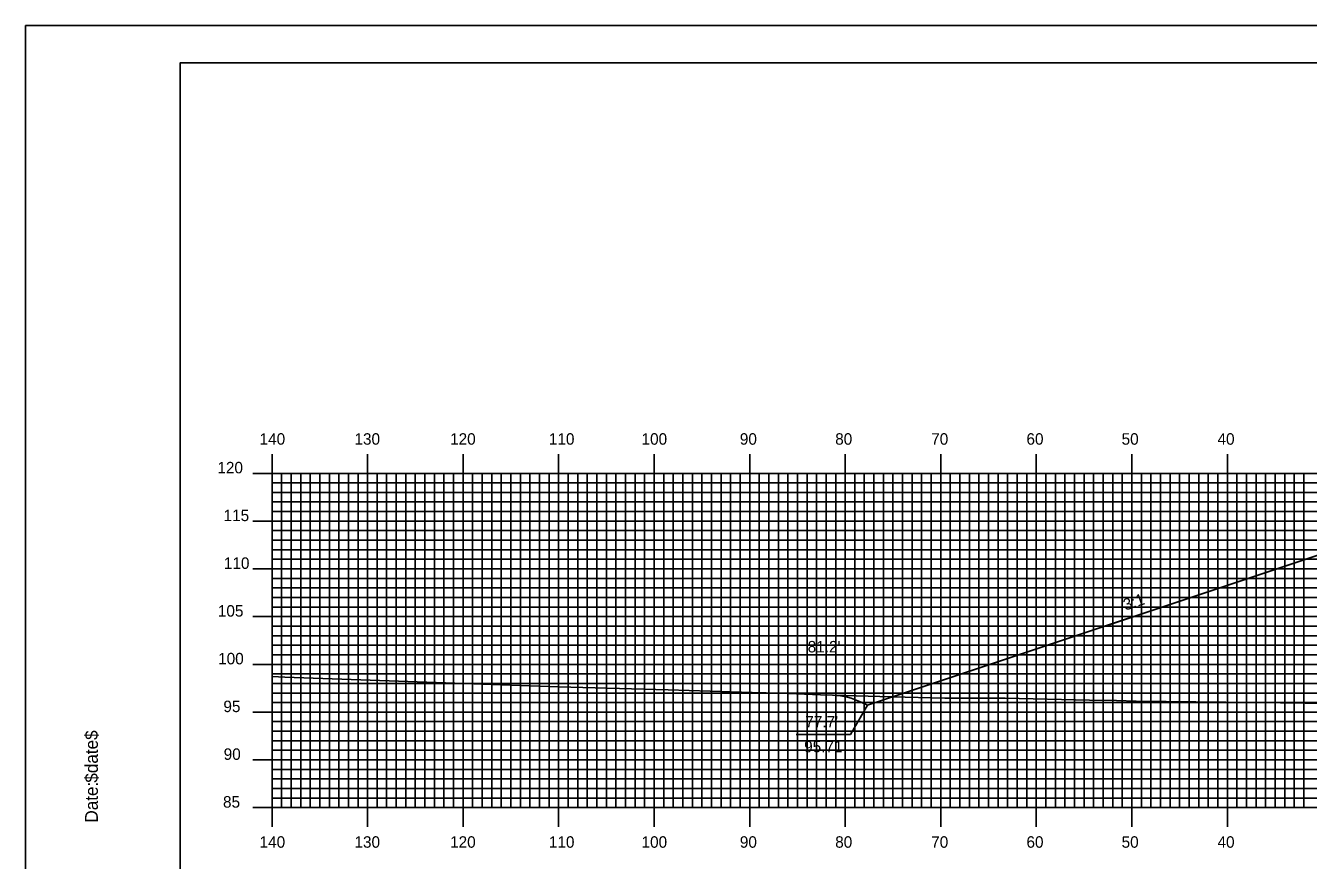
# Model space of a CAD drawing. Extents: x 1786582 to 1786926, y 442591 to 442811.
# Drawn here: x 1786582.3 to 1786716.6, y 442723.1 to 442810.5 of the extents above; entities that cross this region are included whole.
import ezdxf

# ---------------------------------------------------------------- set-up
doc = ezdxf.new("R2010")
doc.units = 0
for name, color, linetype in [('ANNOTATION', 7, 'Continuous'), ('BORDER', 7, 'Continuous'), ('D_Roadway_Centerline', 7, 'Continuous'), ('D_Roadway_FinishedGrade', 7, 'Continuous'), ('D_Roadway_SlopeLines', 7, 'Continuous'), ('D_Text_Standard', 7, 'Continuous'), ('H_V ANNOTATION', 7, 'Continuous'), ('MAJOR', 7, 'Continuous'), ('MINOR', 7, 'Continuous'), ('PLOT BOUNDARY', 7, 'Continuous'), ('S_Roadway_Centerline', 7, 'Continuous')]:
    doc.layers.add(name, color=color, linetype=linetype)

msp = doc.modelspace()

# ---------------------------------------------------------------- linework, layer by layer
at = {"layer": 'ANNOTATION'}
msp.add_lwpolyline([(1786662.93, 442736.34), (1786668.62, 442736.34), (1786670.4, 442739.38)], dxfattribs=at)
at = {"layer": 'BORDER'}
msp.add_lwpolyline([(1786598.48, 442596.67), (1786918.48, 442596.67), (1786918.48, 442806.67), (1786598.48, 442806.67)], close=True, dxfattribs=at)
at = {"layer": 'D_Roadway_Centerline'}
msp.add_lwpolyline([(1786673.07, 442740.26), (1786717.68, 442755.13), (1786725.08, 442757.6), (1786728.08, 442757.72), (1786736.08, 442758.04), (1786748.08, 442758.3), (1786760.08, 442758.57), (1786768.08, 442758.25), (1786771.08, 442758.13), (1786776.83, 442755.73), (1786816.52, 442739.19)], dxfattribs=at)
at = {"layer": 'D_Roadway_FinishedGrade'}
msp.add_line((1786670.4, 442739.38), (1786669.75, 442739.7), dxfattribs=at)
msp.add_arc((1786666.62, 442733.44), 7, 63.4349, 88.3839, dxfattribs=at)
at = {"layer": 'D_Roadway_SlopeLines'}
msp.add_lwpolyline([(1786725.08, 442757.6), (1786670.4, 442739.38)], dxfattribs=at)
at = {"layer": 'MAJOR'}
for p, q in [((1786608.08, 442765.67), (1786608.08, 442763.67)), ((1786618.08, 442765.67), (1786618.08, 442763.67)), ((1786628.08, 442765.67), (1786628.08, 442763.67)), ((1786638.08, 442765.67), (1786638.08, 442763.67)), ((1786648.08, 442765.67), (1786648.08, 442763.67)), ((1786658.08, 442765.67), (1786658.08, 442763.67)), ((1786668.08, 442765.67), (1786668.08, 442763.67)), ((1786678.08, 442765.67), (1786678.08, 442763.67)), ((1786688.08, 442765.67), (1786688.08, 442763.67)), ((1786698.08, 442765.67), (1786698.08, 442763.67)), ((1786708.08, 442765.67), (1786708.08, 442763.67)), ((1786606.07, 442763.67), (1786608.08, 442763.67)), ((1786608.08, 442763.67), (1786888.08, 442763.67)), ((1786608.08, 442728.67), (1786608.08, 442763.67)), ((1786608.08, 442728.67), (1786608.08, 442763.67)), ((1786608.08, 442763.67), (1786888.08, 442763.67)), ((1786618.08, 442728.67), (1786618.08, 442763.67)), ((1786628.08, 442728.67), (1786628.08, 442763.67)), ((1786638.08, 442728.67), (1786638.08, 442763.67)), ((1786648.08, 442728.67), (1786648.08, 442763.67)), ((1786658.08, 442728.67), (1786658.08, 442763.67)), ((1786668.08, 442728.67), (1786668.08, 442763.67)), ((1786678.08, 442728.67), (1786678.08, 442763.67)), ((1786688.08, 442728.67), (1786688.08, 442763.67)), ((1786698.08, 442728.67), (1786698.08, 442763.67)), ((1786708.08, 442728.67), (1786708.08, 442763.67)), ((1786606.07, 442758.67), (1786608.08, 442758.67)), ((1786608.08, 442758.67), (1786888.08, 442758.67)), ((1786606.07, 442753.67), (1786608.08, 442753.67)), ((1786608.08, 442753.67), (1786888.08, 442753.67)), ((1786606.07, 442748.67), (1786608.08, 442748.67)), ((1786608.08, 442748.67), (1786888.08, 442748.67)), ((1786606.07, 442743.67), (1786608.08, 442743.67)), ((1786608.08, 442743.67), (1786888.08, 442743.67)), ((1786606.07, 442738.67), (1786608.08, 442738.67)), ((1786608.08, 442738.67), (1786888.08, 442738.67)), ((1786606.07, 442733.67), (1786608.08, 442733.67)), ((1786608.08, 442733.67), (1786888.08, 442733.67)), ((1786606.07, 442728.67), (1786608.08, 442728.67)), ((1786608.08, 442728.67), (1786888.08, 442728.67)), ((1786608.08, 442728.67), (1786888.08, 442728.67)), ((1786608.08, 442726.66), (1786608.08, 442728.67)), ((1786618.08, 442726.66), (1786618.08, 442728.67)), ((1786628.08, 442726.66), (1786628.08, 442728.67)), ((1786638.08, 442726.66), (1786638.08, 442728.67)), ((1786648.08, 442726.66), (1786648.08, 442728.67)), ((1786658.08, 442726.66), (1786658.08, 442728.67)), ((1786668.08, 442726.66), (1786668.08, 442728.67)), ((1786678.08, 442726.66), (1786678.08, 442728.67)), ((1786688.08, 442726.66), (1786688.08, 442728.67)), ((1786698.08, 442726.66), (1786698.08, 442728.67)), ((1786708.08, 442726.66), (1786708.08, 442728.67))]:
    msp.add_line(p, q, dxfattribs=at)
at = {"layer": 'MINOR'}
for p, q in [((1786609.08, 442728.67), (1786609.08, 442763.67)), ((1786610.08, 442728.67), (1786610.08, 442763.67)), ((1786611.08, 442728.67), (1786611.08, 442763.67)), ((1786612.08, 442728.67), (1786612.08, 442763.67)), ((1786613.08, 442728.67), (1786613.08, 442763.67)), ((1786614.08, 442728.67), (1786614.08, 442763.67)), ((1786615.08, 442728.67), (1786615.08, 442763.67)), ((1786616.08, 442728.67), (1786616.08, 442763.67)), ((1786617.08, 442728.67), (1786617.08, 442763.67)), ((1786619.08, 442728.67), (1786619.08, 442763.67)), ((1786620.08, 442728.67), (1786620.08, 442763.67)), ((1786621.08, 442728.67), (1786621.08, 442763.67)), ((1786622.08, 442728.67), (1786622.08, 442763.67)), ((1786623.08, 442728.67), (1786623.08, 442763.67)), ((1786624.08, 442728.67), (1786624.08, 442763.67)), ((1786625.08, 442728.67), (1786625.08, 442763.67)), ((1786626.08, 442728.67), (1786626.08, 442763.67)), ((1786627.08, 442728.67), (1786627.08, 442763.67)), ((1786629.08, 442728.67), (1786629.08, 442763.67)), ((1786630.08, 442728.67), (1786630.08, 442763.67)), ((1786631.08, 442728.67), (1786631.08, 442763.67)), ((1786632.08, 442728.67), (1786632.08, 442763.67)), ((1786633.08, 442728.67), (1786633.08, 442763.67)), ((1786634.08, 442728.67), (1786634.08, 442763.67)), ((1786635.08, 442728.67), (1786635.08, 442763.67)), ((1786636.08, 442728.67), (1786636.08, 442763.67)), ((1786637.08, 442728.67), (1786637.08, 442763.67)), ((1786639.08, 442728.67), (1786639.08, 442763.67)), ((1786640.08, 442728.67), (1786640.08, 442763.67)), ((1786641.08, 442728.67), (1786641.08, 442763.67)), ((1786642.08, 442728.67), (1786642.08, 442763.67)), ((1786643.08, 442728.67), (1786643.08, 442763.67)), ((1786644.08, 442728.67), (1786644.08, 442763.67)), ((1786645.08, 442728.67), (1786645.08, 442763.67)), ((1786646.08, 442728.67), (1786646.08, 442763.67)), ((1786647.08, 442728.67), (1786647.08, 442763.67)), ((1786649.08, 442728.67), (1786649.08, 442763.67)), ((1786650.08, 442728.67), (1786650.08, 442763.67)), ((1786651.08, 442728.67), (1786651.08, 442763.67)), ((1786652.08, 442728.67), (1786652.08, 442763.67)), ((1786653.08, 442728.67), (1786653.08, 442763.67)), ((1786654.08, 442728.67), (1786654.08, 442763.67)), ((1786655.08, 442728.67), (1786655.08, 442763.67)), ((1786656.08, 442728.67), (1786656.08, 442763.67)), ((1786657.08, 442728.67), (1786657.08, 442763.67)), ((1786659.08, 442728.67), (1786659.08, 442763.67)), ((1786660.08, 442728.67), (1786660.08, 442763.67)), ((1786661.08, 442728.67), (1786661.08, 442763.67)), ((1786662.08, 442728.67), (1786662.08, 442763.67)), ((1786663.08, 442728.67), (1786663.08, 442763.67)), ((1786664.08, 442728.67), (1786664.08, 442763.67)), ((1786665.08, 442728.67), (1786665.08, 442763.67)), ((1786666.08, 442728.67), (1786666.08, 442763.67)), ((1786667.08, 442728.67), (1786667.08, 442763.67)), ((1786669.08, 442728.67), (1786669.08, 442763.67)), ((1786670.08, 442728.67), (1786670.08, 442763.67)), ((1786671.08, 442728.67), (1786671.08, 442763.67)), ((1786672.08, 442728.67), (1786672.08, 442763.67)), ((1786673.08, 442728.67), (1786673.08, 442763.67)), ((1786674.08, 442728.67), (1786674.08, 442763.67)), ((1786675.08, 442728.67), (1786675.08, 442763.67)), ((1786676.08, 442728.67), (1786676.08, 442763.67)), ((1786677.08, 442728.67), (1786677.08, 442763.67)), ((1786679.08, 442728.67), (1786679.08, 442763.67)), ((1786680.08, 442728.67), (1786680.08, 442763.67)), ((1786681.08, 442728.67), (1786681.08, 442763.67)), ((1786682.08, 442728.67), (1786682.08, 442763.67)), ((1786683.08, 442728.67), (1786683.08, 442763.67)), ((1786684.08, 442728.67), (1786684.08, 442763.67)), ((1786685.08, 442728.67), (1786685.08, 442763.67)), ((1786686.08, 442728.67), (1786686.08, 442763.67)), ((1786687.08, 442728.67), (1786687.08, 442763.67)), ((1786689.08, 442728.67), (1786689.08, 442763.67)), ((1786690.08, 442728.67), (1786690.08, 442763.67)), ((1786691.08, 442728.67), (1786691.08, 442763.67)), ((1786692.08, 442728.67), (1786692.08, 442763.67)), ((1786693.08, 442728.67), (1786693.08, 442763.67)), ((1786694.08, 442728.67), (1786694.08, 442763.67)), ((1786695.08, 442728.67), (1786695.08, 442763.67)), ((1786696.08, 442728.67), (1786696.08, 442763.67)), ((1786697.08, 442728.67), (1786697.08, 442763.67)), ((1786699.08, 442728.67), (1786699.08, 442763.67)), ((1786700.08, 442728.67), (1786700.08, 442763.67)), ((1786701.08, 442728.67), (1786701.08, 442763.67)), ((1786702.08, 442728.67), (1786702.08, 442763.67)), ((1786703.08, 442728.67), (1786703.08, 442763.67)), ((1786704.08, 442728.67), (1786704.08, 442763.67)), ((1786705.08, 442728.67), (1786705.08, 442763.67)), ((1786706.08, 442728.67), (1786706.08, 442763.67)), ((1786707.08, 442728.67), (1786707.08, 442763.67)), ((1786709.08, 442728.67), (1786709.08, 442763.67)), ((1786710.08, 442728.67), (1786710.08, 442763.67)), ((1786711.08, 442728.67), (1786711.08, 442763.67)), ((1786712.08, 442728.67), (1786712.08, 442763.67)), ((1786713.08, 442728.67), (1786713.08, 442763.67)), ((1786714.08, 442728.67), (1786714.08, 442763.67)), ((1786715.08, 442728.67), (1786715.08, 442763.67)), ((1786716.08, 442728.67), (1786716.08, 442763.67)), ((1786608.08, 442762.67), (1786888.08, 442762.67)), ((1786608.08, 442762.67), (1786610.08, 442762.67)), ((1786608.08, 442761.67), (1786888.08, 442761.67)), ((1786608.08, 442761.67), (1786610.08, 442761.67)), ((1786608.08, 442760.67), (1786888.08, 442760.67)), ((1786608.08, 442760.67), (1786610.08, 442760.67)), ((1786608.08, 442759.67), (1786888.08, 442759.67)), ((1786608.08, 442759.67), (1786610.08, 442759.67)), ((1786608.08, 442757.67), (1786888.08, 442757.67)), ((1786608.08, 442757.67), (1786610.08, 442757.67)), ((1786608.08, 442756.67), (1786888.08, 442756.67)), ((1786608.08, 442756.67), (1786610.08, 442756.67)), ((1786608.08, 442755.67), (1786888.08, 442755.67)), ((1786608.08, 442755.67), (1786610.08, 442755.67)), ((1786608.08, 442754.67), (1786888.08, 442754.67)), ((1786608.08, 442754.67), (1786610.08, 442754.67)), ((1786608.08, 442752.67), (1786888.08, 442752.67)), ((1786608.08, 442752.67), (1786610.08, 442752.67)), ((1786608.08, 442751.67), (1786888.08, 442751.67)), ((1786608.08, 442751.67), (1786610.08, 442751.67)), ((1786608.08, 442750.67), (1786888.08, 442750.67)), ((1786608.08, 442750.67), (1786610.08, 442750.67)), ((1786608.08, 442749.67), (1786888.08, 442749.67)), ((1786608.08, 442749.67), (1786610.08, 442749.67)), ((1786608.08, 442747.67), (1786888.08, 442747.67)), ((1786608.08, 442747.67), (1786610.08, 442747.67)), ((1786608.08, 442746.67), (1786888.08, 442746.67)), ((1786608.08, 442746.67), (1786610.08, 442746.67)), ((1786608.08, 442745.67), (1786888.08, 442745.67)), ((1786608.08, 442745.67), (1786610.08, 442745.67)), ((1786608.08, 442744.67), (1786888.08, 442744.67)), ((1786608.08, 442744.67), (1786610.08, 442744.67)), ((1786608.08, 442742.67), (1786888.08, 442742.67)), ((1786608.08, 442742.67), (1786610.08, 442742.67)), ((1786608.08, 442741.67), (1786888.08, 442741.67)), ((1786608.08, 442741.67), (1786610.08, 442741.67)), ((1786608.08, 442740.67), (1786888.08, 442740.67)), ((1786608.08, 442740.67), (1786610.08, 442740.67)), ((1786608.08, 442739.67), (1786888.08, 442739.67)), ((1786608.08, 442739.67), (1786610.08, 442739.67)), ((1786608.08, 442737.67), (1786888.08, 442737.67)), ((1786608.08, 442737.67), (1786610.08, 442737.67)), ((1786608.08, 442736.67), (1786888.08, 442736.67)), ((1786608.08, 442736.67), (1786610.08, 442736.67)), ((1786608.08, 442735.67), (1786888.08, 442735.67)), ((1786608.08, 442735.67), (1786610.08, 442735.67)), ((1786608.08, 442734.67), (1786888.08, 442734.67)), ((1786608.08, 442734.67), (1786610.08, 442734.67)), ((1786608.08, 442732.67), (1786888.08, 442732.67)), ((1786608.08, 442732.67), (1786610.08, 442732.67)), ((1786608.08, 442731.67), (1786888.08, 442731.67)), ((1786608.08, 442731.67), (1786610.08, 442731.67)), ((1786608.08, 442730.67), (1786888.08, 442730.67)), ((1786608.08, 442730.67), (1786610.08, 442730.67)), ((1786608.08, 442729.67), (1786888.08, 442729.67)), ((1786608.08, 442729.67), (1786610.08, 442729.67))]:
    msp.add_line(p, q, dxfattribs=at)
at = {"layer": 'PLOT BOUNDARY'}
msp.add_lwpolyline([(1786582.29, 442590.55), (1786922.29, 442590.55), (1786922.29, 442810.55), (1786582.29, 442810.55)], close=True, dxfattribs=at)
at = {"layer": 'S_Roadway_Centerline'}
msp.add_lwpolyline([(1786608.08, 442742.39), (1786609.43, 442742.32), (1786618.36, 442742.01), (1786637.09, 442741.35), (1786638.06, 442741.31), (1786649.55, 442740.99), (1786658.34, 442740.71), (1786661.31, 442740.64), (1786665.49, 442740.48), (1786672.97, 442740.27), (1786678.49, 442740.14), (1786684.81, 442740.12), (1786693.65, 442739.92), (1786696.47, 442739.88), (1786698.54, 442739.83), (1786711.06, 442739.68), (1786718.81, 442739.58)], dxfattribs=at)

# ---------------------------------------------------------------- texts
at = {"layer": 'ANNOTATION'}
msp.add_text('3:1', height=1.2, rotation=18.4349, dxfattribs=at).set_placement((1786697.41, 442749.29))
for s, p in [("77.7' ", (1786663.9, 442737.06)), ('95.71', (1786663.78, 442734.46))]:
    msp.add_text(s, height=1.2, dxfattribs=at).set_placement(p)
at = {"layer": 'BORDER'}
for s, p in [('$date$', (1786589.85, 442731.28)), ('Date:', (1786589.85, 442727.1))]:
    msp.add_text(s, height=1.339, rotation=90, dxfattribs=at).set_placement(p)
at = {"layer": 'D_Text_Standard'}
msp.add_text("81.2'", height=1.2, dxfattribs=at).set_placement((1786664.15, 442744.92))
at = {"layer": 'H_V ANNOTATION'}
for s, p in [('140', (1786606.78, 442766.67)), ('130', (1786616.71, 442766.67)), ('120', (1786626.72, 442766.67)), ('110', (1786637.06, 442766.67)), ('100', (1786646.76, 442766.67)), ('90', (1786657.05, 442766.67)), ('80', (1786667.03, 442766.67)), ('70', (1786677.08, 442766.67)), ('60', (1786687.05, 442766.67)), ('50', (1786697.01, 442766.67)), ('40', (1786707.05, 442766.67)), ('120', (1786602.36, 442763.67)), ('115', (1786603.01, 442758.67)), ('110', (1786603.04, 442753.67)), ('105', (1786602.41, 442748.67)), ('100', (1786602.44, 442743.67)), ('95', (1786602.99, 442738.67)), ('90', (1786603.02, 442733.67)), ('85', (1786602.95, 442728.67)), ('140', (1786606.78, 442724.47)), ('130', (1786616.71, 442724.47)), ('120', (1786626.72, 442724.47)), ('110', (1786637.06, 442724.47)), ('100', (1786646.76, 442724.47)), ('90', (1786657.05, 442724.47)), ('80', (1786667.03, 442724.47)), ('70', (1786677.08, 442724.47)), ('60', (1786687.05, 442724.47)), ('50', (1786697.01, 442724.47)), ('40', (1786707.05, 442724.47))]:
    msp.add_text(s, height=1.2, dxfattribs=at).set_placement(p)
at = {"layer": 'MAJOR'}
msp.add_text('-', height=0.012, dxfattribs=at).set_placement((1786608.07, 442728.67))

doc.saveas('drawing.dxf')
